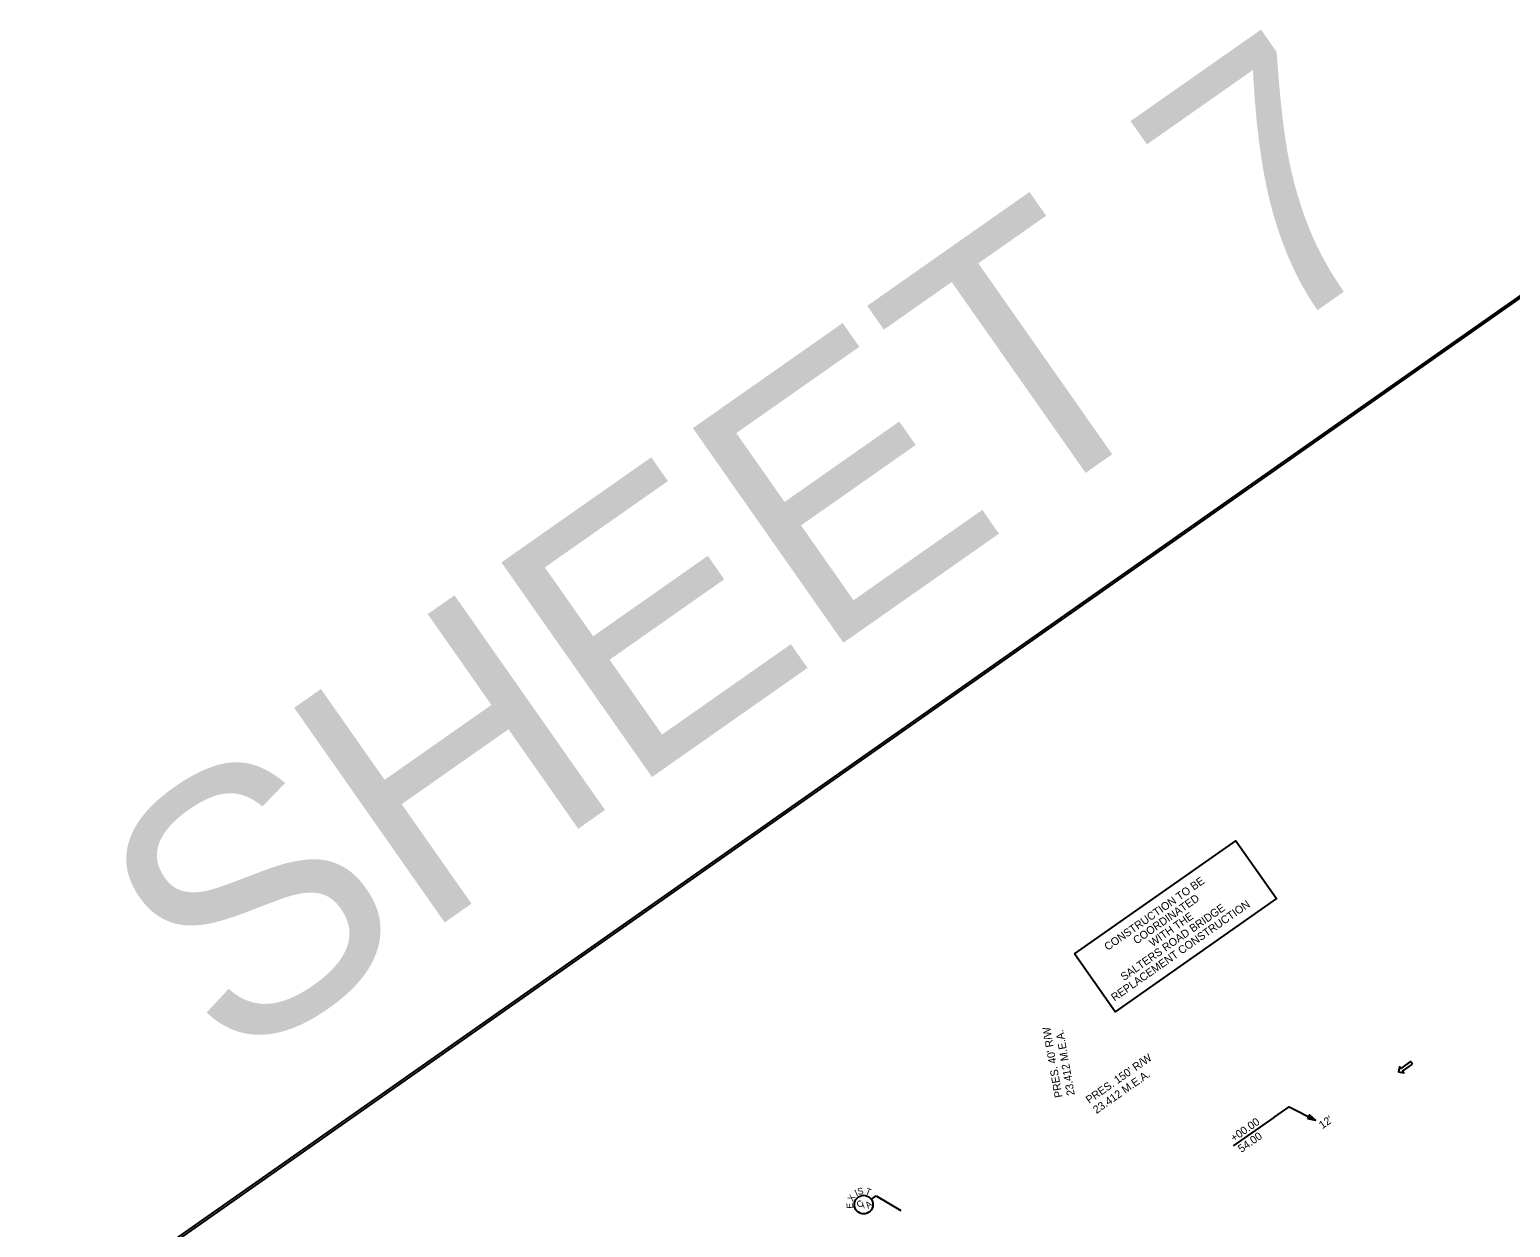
# Model space of a CAD drawing. Extents: x 1603735 to 1605655, y 1088656 to 1090462.
# Drawn here: x 1603735 to 1604864, y 1089549 to 1090462 of the extents above; entities that cross this region are included whole.
import ezdxf

# ---------------------------------------------------------------- set-up
doc = ezdxf.new("R2010")
doc.units = 0
for name, color, linetype in [('RD_EX_BldgApp', 7, 'Continuous'), ('RD_EX_Fence_Other', 7, 'Continuous'), ('RD_EX_Misc', 7, 'Continuous'), ('RD_EX_Misc_Golf_Teebox', 7, 'Continuous'), ('RD_EX_Road', 7, 'Continuous'), ('RD_EX_UT', 7, 'Continuous'), ('RD_HC_SUR_CL400', 7, 'Continuous')]:
    doc.layers.add(name, color=color, linetype=linetype)

msp = doc.modelspace()

# ---------------------------------------------------------------- linework, layer by layer
at = {"layer": 'RD_EX_Fence_Other'}
msp.add_lwpolyline([(1603734.7, 1089461.6), (1605106, 1090423.5), (1605655.3, 1089640.4), (1604284, 1088678.5)], close=True, dxfattribs=at)
at = {"layer": 'RD_EX_Misc'}
msp.add_lwpolyline([(1604789.6, 1089673.3), (1604788.3, 1089675.3), (1604780.8, 1089670), (1604779.8, 1089671.3), (1604779.1, 1089667.4), (1604783.1, 1089666.7), (1604782.1, 1089668)], close=True, dxfattribs=at)
at = {"layer": 'RD_EX_Misc_Golf_Teebox'}
msp.add_line((1604683.9, 1089632.5), (1604653, 1089610.9), dxfattribs=at)
for points in [[(1604531.9, 1089757.3), (1604655, 1089843.6), (1604685.9, 1089799.5), (1604562.8, 1089713.1)], [(1604709.7, 1089631.7), (1604715.6, 1089630.5), (1604711.1, 1089634.5)]]:
    msp.add_lwpolyline(points, close=True, dxfattribs=at)
msp.add_lwpolyline([(1604683.9, 1089632.5), (1604695.5, 1089640.7), (1604715.6, 1089630.5)], dxfattribs=at)
at = {"layer": 'RD_EX_UT'}
msp.add_lwpolyline([(1605233.6, 1090111), (1605405.8, 1089865.4), (1605593.1, 1089598.4), (1604362.4, 1088735.2), (1604177.8, 1089004.1), (1604005.5, 1089249.7), (1603817.5, 1089517.8), (1604919, 1090290.5), (1604939.8, 1090260.9), (1605067.4, 1090350.4)], close=True, dxfattribs=at)
msp.add_lwpolyline([(1605233.6, 1090111), (1605405.8, 1089865.4), (1605593.1, 1089598.4), (1604362.4, 1088735.2), (1604177.8, 1089004.1), (1604005.5, 1089249.7), (1603817.5, 1089517.8), (1604919, 1090290.5), (1604939.8, 1090260.9), (1605067.4, 1090350.4)], close=True, dxfattribs=at)
msp.add_lwpolyline([(1605233.6, 1090111), (1605405.8, 1089865.4), (1605593.1, 1089598.4), (1604362.4, 1088735.2), (1604177.8, 1089004.1), (1604005.5, 1089249.7), (1603817.5, 1089517.8), (1604919, 1090290.5), (1604939.8, 1090260.9), (1605067.4, 1090350.4)], close=True, dxfattribs=at)
at = {"layer": 'RD_HC_SUR_CL400'}
for p, q in [((1604376.8, 1089570.1), (1604380.6, 1089572.8)), ((1604380.6, 1089572.8), (1604399.3, 1089561.6))]:
    msp.add_line(p, q, dxfattribs=at)
msp.add_circle((1604371, 1089566.1), 7.08, dxfattribs=at)

# ---------------------------------------------------------------- texts
at = {"layer": 'RD_EX_BldgApp'}
for s, rotation, p in [("PRES. 40' R/W", 100.0806, (1604522.8, 1089648.2)), ('23.412 M.E.A.', 100.0806, (1604532.1, 1089649.8)), ("PRES. 150' R/W", 35.0468, (1604543.1, 1089642.8)), ('23.412 M.E.A.', 35.0468, (1604548.6, 1089635.1))]:
    msp.add_text(s, height=6, rotation=rotation, dxfattribs=at).set_placement(p)
at = {"layer": 'RD_EX_Misc_Golf_Teebox'}
for s, rotation, p in [('CONSTRUCTION TO BE', 35.0468, (1604557.2, 1089759.5)), ('COORDINATED', 35.0468, (1604579.2, 1089764.4)), ('REPLACEMENT CONSTRUCTION', 35.0468, (1604562.4, 1089720.9)), ('SALTERS ROAD BRIDGE', 35.0468, (1604569.6, 1089736.6)), ('WITH THE', 35.0468, (1604591.5, 1089762.5)), ("12'", 35.0436, (1604720.9, 1089623.5)), ('+00.00', 35.0468, (1604653.5, 1089613.7)), ('54.00', 35.0468, (1604659.2, 1089605.5))]:
    msp.add_text(s, height=6, rotation=rotation, dxfattribs=at).set_placement(p)
at = {"layer": 'RD_EX_Road'}
msp.add_text('SHEET 7', height=200, rotation=35.0468, dxfattribs=at).set_placement((1603887.4, 1089666.3))
at = {"layer": 'RD_HC_SUR_CL400'}
for s, rotation, p in [('I', 24.9789, (1604365.5, 1089572.4)), ('S', 13.2584, (1604366.9, 1089573.4)), ('T', 338.0969, (1604371.8, 1089574.4)), ('E', 93.6275, (1604363.1, 1089563.2)), ('X', 60.1403, (1604362.8, 1089568)), ('C', 35.0436, (1604367.7, 1089563.2)), ('/', 35.0436, (1604371.3, 1089563.2)), ('A', 35.0436, (1604374.4, 1089562.8))]:
    msp.add_text(s, height=5, rotation=rotation, dxfattribs=at).set_placement(p)

doc.saveas('drawing.dxf')
